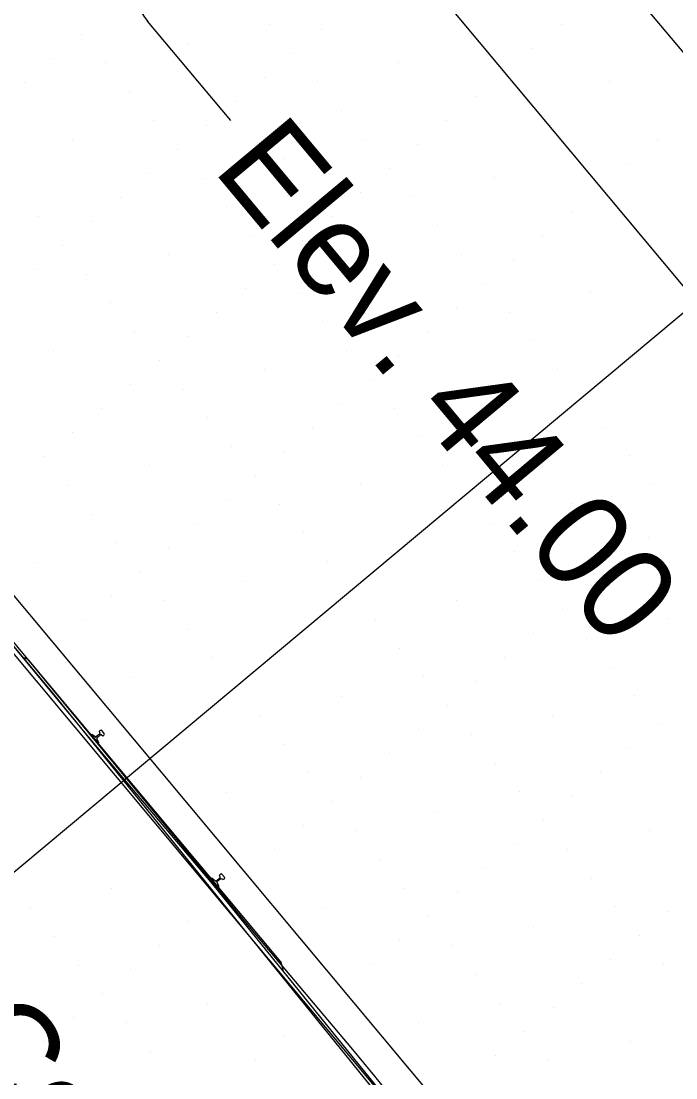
# Model space of a CAD drawing. Extents: x 2042995 to 2043795, y 305365 to 306249.
# Drawn here: x 2043333.05 to 2043350.52, y 305730.9 to 305759.09 of the extents above; entities that cross this region are included whole.
import ezdxf

# ---------------------------------------------------------------- set-up
doc = ezdxf.new("R2010")
doc.units = 0
for name, color, linetype in [('BR_AUTO DIMENSION', 7, 'Continuous'), ('BR_CONCRETE', 7, 'Continuous'), ('BR_EXIST_GROUND_CL', 7, 'Continuous'), ('BR_EXIST_GROUND_LT', 7, 'Continuous'), ('BR_EXIST_GROUND_RT', 7, 'Continuous'), ('BR_GRID DOTS', 7, 'Continuous'), ('BR_GRID LINES', 7, 'Continuous'), ('BR_GROUND LINES', 7, 'Continuous'), ('BR_PRESTRESSED BEAM', 7, 'Continuous'), ('BR_STRUCTURAL STEEL', 7, 'Continuous'), ('BR_TEXT', 7, 'Continuous')]:
    doc.layers.add(name, color=color, linetype=linetype)

msp = doc.modelspace()

# ---------------------------------------------------------------- linework, layer by layer
at = {"layer": 'BR_AUTO DIMENSION'}
for p, q in [((2043320.869, 305793.992), (2043366.621, 305739.212)), ((2043303.216, 305779.248), (2043348.968, 305724.468)), ((2043338.646, 305756.435), (2043336.429, 305759.091))]:
    msp.add_line(p, q, dxfattribs=at)
msp.add_arc((2043337.708, 305760.159), 1.667, 129.8684, 219.8684, dxfattribs=at)
at = {"layer": 'BR_CONCRETE'}
for points in [[(2043139.109, 306017.548), (2043148.199, 306007.16), (2043160.233, 305993.368), (2043172.245, 305979.557), (2043184.234, 305965.727), (2043196.201, 305951.879), (2043208.145, 305938.012), (2043220.067, 305924.126), (2043231.966, 305910.221), (2043243.843, 305896.297), (2043255.698, 305882.355), (2043267.529, 305868.394), (2043279.339, 305854.414), (2043291.126, 305840.415), (2043302.89, 305826.398), (2043314.632, 305812.361), (2043326.352, 305798.306), (2043338.049, 305784.233), (2043349.724, 305770.14), (2043361.376, 305756.029), (2043373.005, 305741.899), (2043384.613, 305727.75), (2043396.197, 305713.582), (2043407.76, 305699.396), (2043419.299, 305685.191), (2043430.817, 305670.967), (2043442.311, 305656.724), (2043453.784, 305642.463), (2043465.234, 305628.182), (2043476.661, 305613.883), (2043488.066, 305599.566), (2043499.448, 305585.229), (2043510.808, 305570.874), (2043522.146, 305556.5), (2043533.461, 305542.107), (2043544.753, 305527.695), (2043547.219, 305524.543)], [(2043273.14, 305860.139), (2043278.86, 305853.362), (2043290.647, 305839.364), (2043302.411, 305825.346), (2043314.153, 305811.31), (2043325.873, 305797.255), (2043337.57, 305783.181), (2043349.245, 305769.089), (2043360.897, 305754.977), (2043372.526, 305740.847), (2043384.134, 305726.698), (2043395.718, 305712.531), (2043407.281, 305698.344), (2043418.82, 305684.139), (2043425.623, 305675.744)]]:
    msp.add_spline(points, degree=3, dxfattribs=at)
at = {"layer": 'BR_EXIST_GROUND_CL'}
msp.add_lwpolyline([(2043308.08, 305802.975), (2043311.357, 305794.254), (2043312.201, 305793.367), (2043312.31, 305791.765), (2043310.711, 305789.675), (2043302.424, 305778.884), (2043307.323, 305773.564), (2043309.247, 305771.475), (2043312.233, 305767.935), (2043312.545, 305767.564), (2043317.632, 305761.139), (2043321.959, 305755.674), (2043324.878, 305751.989), (2043325.714, 305750.99), (2043328.169, 305748.055), (2043331.001, 305744.638), (2043334.846, 305739.998), (2043336.813, 305737.66), (2043338.156, 305736.064), (2043343.356, 305729.655)], dxfattribs=at)
at = {"layer": 'BR_EXIST_GROUND_LT'}
msp.add_lwpolyline([(2043306.871, 305795.372), (2043298.097, 305784.008), (2043302.538, 305779.189), (2043304.941, 305776.583), (2043307.803, 305773.186), (2043308.238, 305772.67), (2043315.324, 305763.737), (2043320.576, 305757.115), (2043320.901, 305756.726), (2043323.864, 305753.181), (2043328.979, 305747.048), (2043330.565, 305745.131), (2043331.485, 305744.037), (2043333.871, 305741.191), (2043345.181, 305727.208)], dxfattribs=at)
at = {"layer": 'BR_EXIST_GROUND_RT'}
msp.add_lwpolyline([(2043311.795, 305797.361), (2043312.912, 305786.83), (2043313.335, 305784.229), (2043315.447, 305785.237), (2043313.716, 305783.437), (2043313.135, 305782.673), (2043309.838, 305778.182), (2043306.75, 305773.76), (2043310.033, 305770.195), (2043313.561, 305766.363), (2043315.546, 305764.008), (2043316.86, 305762.451), (2043321.605, 305756.461), (2043329.201, 305746.882), (2043331.305, 305744.369), (2043332.491, 305742.951), (2043337.468, 305736.946), (2043339.175, 305734.886), (2043341.892, 305731.649), (2043342.483, 305730.946), (2043346.769, 305725.658)], dxfattribs=at)
at = {"layer": 'BR_GRID DOTS'}
for p, q in [((2043339.667, 305759.004), (2043339.667, 305759.004)), ((2043341.075, 305758.878), (2043341.075, 305758.878)), ((2043347.477, 305759.013), (2043347.477, 305759.013)), ((2043334.674, 305758.743), (2043334.674, 305758.743)), ((2043337.491, 305758.49), (2043337.491, 305758.49)), ((2043350.294, 305758.76), (2043350.294, 305758.76)), ((2043340.308, 305758.237), (2043340.308, 305758.237)), ((2043346.709, 305758.372), (2043346.709, 305758.372)), ((2043333.906, 305758.102), (2043333.906, 305758.102)), ((2043335.315, 305757.975), (2043335.315, 305757.975)), ((2043343.125, 305757.984), (2043343.125, 305757.984)), ((2043345.942, 305757.731), (2043345.942, 305757.731)), ((2043333.139, 305757.461), (2043333.139, 305757.461)), ((2043339.54, 305757.596), (2043339.54, 305757.596)), ((2043340.949, 305757.469), (2043340.949, 305757.469)), ((2043348.759, 305757.478), (2043348.759, 305757.478)), ((2043335.956, 305757.208), (2043335.956, 305757.208)), ((2043345.174, 305757.09), (2043345.174, 305757.09)), ((2043338.773, 305756.955), (2043338.773, 305756.955)), ((2043341.59, 305756.702), (2043341.59, 305756.702)), ((2043336.597, 305756.44), (2043336.597, 305756.44)), ((2043338.005, 305756.314), (2043338.005, 305756.314)), ((2043344.407, 305756.449), (2043344.407, 305756.449)), ((2043334.421, 305755.926), (2043334.421, 305755.926)), ((2043337.238, 305755.673), (2043337.238, 305755.673)), ((2043342.231, 305755.934), (2043342.231, 305755.934)), ((2043343.639, 305755.808), (2043343.639, 305755.808)), ((2043350.041, 305755.943), (2043350.041, 305755.943)), ((2043340.055, 305755.42), (2043340.055, 305755.42)), ((2043342.872, 305755.167), (2043342.872, 305755.167)), ((2043349.274, 305755.302), (2043349.274, 305755.302)), ((2043336.47, 305755.032), (2043336.47, 305755.032)), ((2043337.879, 305754.905), (2043337.879, 305754.905)), ((2043345.689, 305754.914), (2043345.689, 305754.914)), ((2043348.506, 305754.661), (2043348.506, 305754.661)), ((2043335.703, 305754.391), (2043335.703, 305754.391)), ((2043342.104, 305754.526), (2043342.104, 305754.526)), ((2043343.513, 305754.399), (2043343.513, 305754.399)), ((2043338.52, 305754.138), (2043338.52, 305754.138)), ((2043347.739, 305754.02), (2043347.739, 305754.02)), ((2043333.527, 305753.876), (2043333.527, 305753.876)), ((2043334.935, 305753.75), (2043334.935, 305753.75)), ((2043341.337, 305753.885), (2043341.337, 305753.885)), ((2043344.154, 305753.632), (2043344.154, 305753.632)), ((2043339.161, 305753.37), (2043339.161, 305753.37)), ((2043340.569, 305753.244), (2043340.569, 305753.244)), ((2043346.971, 305753.379), (2043346.971, 305753.379)), ((2043334.168, 305753.109), (2043334.168, 305753.109)), ((2043336.985, 305752.856), (2043336.985, 305752.856)), ((2043344.795, 305752.864), (2043344.795, 305752.864)), ((2043339.802, 305752.603), (2043339.802, 305752.603)), ((2043346.203, 305752.738), (2043346.203, 305752.738)), ((2043333.4, 305752.468), (2043333.4, 305752.468)), ((2043334.809, 305752.341), (2043334.809, 305752.341)), ((2043342.619, 305752.35), (2043342.619, 305752.35)), ((2043345.436, 305752.097), (2043345.436, 305752.097)), ((2043339.034, 305751.962), (2043339.034, 305751.962)), ((2043340.443, 305751.835), (2043340.443, 305751.835)), ((2043348.253, 305751.844), (2043348.253, 305751.844)), ((2043335.45, 305751.574), (2043335.45, 305751.574)), ((2043344.668, 305751.456), (2043344.668, 305751.456)), ((2043338.267, 305751.321), (2043338.267, 305751.321)), ((2043346.077, 305751.329), (2043346.077, 305751.329)), ((2043341.084, 305751.068), (2043341.084, 305751.068)), ((2043336.091, 305750.806), (2043336.091, 305750.806)), ((2043337.499, 305750.68), (2043337.499, 305750.68)), ((2043343.901, 305750.815), (2043343.901, 305750.815)), ((2043346.718, 305750.562), (2043346.718, 305750.562)), ((2043333.915, 305750.292), (2043333.915, 305750.292)), ((2043336.732, 305750.039), (2043336.732, 305750.039)), ((2043341.725, 305750.3), (2043341.725, 305750.3)), ((2043343.133, 305750.174), (2043343.133, 305750.174)), ((2043339.549, 305749.786), (2043339.549, 305749.786)), ((2043347.359, 305749.794), (2043347.359, 305749.794)), ((2043342.366, 305749.533), (2043342.366, 305749.533)), ((2043335.964, 305749.398), (2043335.964, 305749.398)), ((2043337.373, 305749.271), (2043337.373, 305749.271)), ((2043345.183, 305749.28), (2043345.183, 305749.28)), ((2043335.197, 305748.757), (2043335.197, 305748.757)), ((2043341.598, 305748.892), (2043341.598, 305748.892)), ((2043343.007, 305748.765), (2043343.007, 305748.765)), ((2043338.014, 305748.504), (2043338.014, 305748.504)), ((2043334.429, 305748.116), (2043334.429, 305748.116)), ((2043340.831, 305748.251), (2043340.831, 305748.251)), ((2043348.641, 305748.259), (2043348.641, 305748.259)), ((2043343.648, 305747.998), (2043343.648, 305747.998)), ((2043338.655, 305747.736), (2043338.655, 305747.736)), ((2043340.063, 305747.61), (2043340.063, 305747.61)), ((2043349.282, 305747.492), (2043349.282, 305747.492)), ((2043333.662, 305747.475), (2043333.662, 305747.475)), ((2043336.479, 305747.222), (2043336.479, 305747.222)), ((2043344.289, 305747.23), (2043344.289, 305747.23)), ((2043339.296, 305746.969), (2043339.296, 305746.969)), ((2043334.303, 305746.707), (2043334.303, 305746.707)), ((2043342.113, 305746.716), (2043342.113, 305746.716)), ((2043349.923, 305746.724), (2043349.923, 305746.724)), ((2043338.528, 305746.328), (2043338.528, 305746.328)), ((2043339.937, 305746.201), (2043339.937, 305746.201)), ((2043347.747, 305746.21), (2043347.747, 305746.21)), ((2043334.944, 305745.94), (2043334.944, 305745.94)), ((2043337.761, 305745.687), (2043337.761, 305745.687)), ((2043345.571, 305745.695), (2043345.571, 305745.695)), ((2043340.578, 305745.434), (2043340.578, 305745.434)), ((2043349.797, 305745.316), (2043349.797, 305745.316)), ((2043335.585, 305745.172), (2043335.585, 305745.172)), ((2043336.993, 305745.045), (2043336.993, 305745.045)), ((2043346.212, 305744.928), (2043346.212, 305744.928)), ((2043349.029, 305744.675), (2043349.029, 305744.675)), ((2043333.409, 305744.657), (2043333.409, 305744.657)), ((2043336.226, 305744.404), (2043336.226, 305744.404)), ((2043341.219, 305744.666), (2043341.219, 305744.666)), ((2043339.043, 305744.151), (2043339.043, 305744.151)), ((2043346.853, 305744.16), (2043346.853, 305744.16)), ((2043348.262, 305744.034), (2043348.262, 305744.034)), ((2043335.458, 305743.763), (2043335.458, 305743.763)), ((2043336.867, 305743.637), (2043336.867, 305743.637)), ((2043344.677, 305743.646), (2043344.677, 305743.646)), ((2043347.494, 305743.393), (2043347.494, 305743.393)), ((2043334.691, 305743.122), (2043334.691, 305743.122)), ((2043342.501, 305743.131), (2043342.501, 305743.131)), ((2043350.311, 305743.14), (2043350.311, 305743.14)), ((2043337.508, 305742.869), (2043337.508, 305742.869)), ((2043346.727, 305742.751), (2043346.727, 305742.751)), ((2043333.923, 305742.481), (2043333.923, 305742.481)), ((2043348.135, 305742.625), (2043348.135, 305742.625)), ((2043343.142, 305742.363), (2043343.142, 305742.363)), ((2043338.149, 305742.102), (2043338.149, 305742.102)), ((2043345.959, 305742.11), (2043345.959, 305742.11)), ((2043348.776, 305741.857), (2043348.776, 305741.857)), ((2043333.156, 305741.84), (2043333.156, 305741.84)), ((2043335.973, 305741.587), (2043335.973, 305741.587)), ((2043343.783, 305741.596), (2043343.783, 305741.596)), ((2043345.192, 305741.469), (2043345.192, 305741.469)), ((2043341.607, 305741.081), (2043341.607, 305741.081)), ((2043349.417, 305741.09), (2043349.417, 305741.09)), ((2043344.424, 305740.828), (2043344.424, 305740.828)), ((2043339.431, 305740.567), (2043339.431, 305740.567)), ((2043347.241, 305740.575), (2043347.241, 305740.575)), ((2043343.656, 305740.187), (2043343.656, 305740.187)), ((2043350.058, 305740.322), (2043350.058, 305740.322)), ((2043345.065, 305740.061), (2043345.065, 305740.061)), ((2043340.072, 305739.799), (2043340.072, 305739.799)), ((2043349.291, 305739.681), (2043349.291, 305739.681)), ((2043342.889, 305739.546), (2043342.889, 305739.546)), ((2043345.706, 305739.293), (2043345.706, 305739.293)), ((2043348.523, 305739.04), (2043348.523, 305739.04)), ((2043340.713, 305739.032), (2043340.713, 305739.032)), ((2043342.121, 305738.905), (2043342.121, 305738.905)), ((2043338.537, 305738.517), (2043338.537, 305738.517)), ((2043346.347, 305738.526), (2043346.347, 305738.526)), ((2043341.354, 305738.264), (2043341.354, 305738.264)), ((2043347.756, 305738.399), (2043347.756, 305738.399)), ((2043344.171, 305738.011), (2043344.171, 305738.011)), ((2043340.586, 305737.623), (2043340.586, 305737.623)), ((2043346.988, 305737.758), (2043346.988, 305737.758)), ((2043341.995, 305737.497), (2043341.995, 305737.497)), ((2043349.805, 305737.505), (2043349.805, 305737.505)), ((2043346.221, 305737.117), (2043346.221, 305737.117)), ((2043339.819, 305736.982), (2043339.819, 305736.982)), ((2043347.629, 305736.991), (2043347.629, 305736.991)), ((2043342.636, 305736.729), (2043342.636, 305736.729)), ((2043339.051, 305736.341), (2043339.051, 305736.341)), ((2043345.453, 305736.476), (2043345.453, 305736.476)), ((2043348.27, 305736.223), (2043348.27, 305736.223)), ((2043335.467, 305735.953), (2043335.467, 305735.953)), ((2043343.277, 305735.962), (2043343.277, 305735.962)), ((2043338.284, 305735.7), (2043338.284, 305735.7)), ((2043344.686, 305735.835), (2043344.686, 305735.835)), ((2043333.291, 305735.439), (2043333.291, 305735.439)), ((2043341.101, 305735.447), (2043341.101, 305735.447)), ((2043348.911, 305735.456), (2043348.911, 305735.456)), ((2043343.918, 305735.194), (2043343.918, 305735.194)), ((2043350.32, 305735.329), (2043350.32, 305735.329)), ((2043337.516, 305735.059), (2043337.516, 305735.059)), ((2043346.735, 305734.941), (2043346.735, 305734.941)), ((2043333.932, 305734.671), (2043333.932, 305734.671)), ((2043343.151, 305734.553), (2043343.151, 305734.553)), ((2043349.552, 305734.688), (2043349.552, 305734.688)), ((2043336.749, 305734.418), (2043336.749, 305734.418)), ((2043344.559, 305734.427), (2043344.559, 305734.427)), ((2043348.785, 305734.047), (2043348.785, 305734.047)), ((2043334.573, 305733.904), (2043334.573, 305733.904)), ((2043335.981, 305733.777), (2043335.981, 305733.777)), ((2043342.383, 305733.912), (2043342.383, 305733.912)), ((2043350.193, 305733.921), (2043350.193, 305733.921)), ((2043345.2, 305733.659), (2043345.2, 305733.659)), ((2043348.017, 305733.406), (2043348.017, 305733.406)), ((2043335.214, 305733.136), (2043335.214, 305733.136)), ((2043341.615, 305733.271), (2043341.615, 305733.271)), ((2043338.031, 305732.883), (2043338.031, 305732.883)), ((2043345.841, 305732.892), (2043345.841, 305732.892)), ((2043340.848, 305732.63), (2043340.848, 305732.63)), ((2043347.25, 305732.765), (2043347.25, 305732.765)), ((2043334.446, 305732.495), (2043334.446, 305732.495)), ((2043335.855, 305732.369), (2043335.855, 305732.369)), ((2043343.665, 305732.377), (2043343.665, 305732.377)), ((2043340.08, 305731.989), (2043340.08, 305731.989)), ((2043346.482, 305732.124), (2043346.482, 305732.124)), ((2043333.679, 305731.854), (2043333.679, 305731.854)), ((2043349.299, 305731.871), (2043349.299, 305731.871)), ((2043336.496, 305731.601), (2043336.496, 305731.601)), ((2043345.715, 305731.483), (2043345.715, 305731.483)), ((2043339.313, 305731.348), (2043339.313, 305731.348)), ((2043347.123, 305731.357), (2043347.123, 305731.357))]:
    msp.add_line(p, q, dxfattribs=at)
at = {"layer": 'BR_GRID LINES'}
for p, q in [((2043122.438, 306025.339), (2043554.061, 305508.544)), ((2043194.694, 305907.624), (2043538.711, 305495.723)), ((2043412.472, 305802.873), (2043258.968, 305674.668))]:
    msp.add_line(p, q, dxfattribs=at)
at = {"layer": 'BR_GROUND LINES'}
for p, q in [((2043333.253, 305742.049), (2043333.087, 305742.121)), ((2043339.984, 305733.99), (2043333.253, 305742.049)), ((2043339.984, 305733.99), (2043340.043, 305733.738))]:
    msp.add_line(p, q, dxfattribs=at)
at = {"layer": 'BR_PRESTRESSED BEAM'}
msp.add_spline([(2043269.336, 305856.962), (2043274.734, 305850.568), (2043286.521, 305836.569), (2043298.285, 305822.551), (2043310.027, 305808.515), (2043321.747, 305794.46), (2043333.444, 305780.386), (2043345.119, 305766.294), (2043356.771, 305752.183), (2043368.4, 305738.053), (2043380.007, 305723.904), (2043391.592, 305709.736), (2043403.154, 305695.55), (2043414.694, 305681.345), (2043421.811, 305672.561)], degree=3, dxfattribs=at)
at = {"layer": 'BR_STRUCTURAL STEEL'}
for p, q in [((2043335.17, 305740.168), (2043335.139, 305740.143)), ((2043335.273, 305740.085), (2043335.206, 305740.165)), ((2043334.936, 305740.062), (2043334.926, 305740.053)), ((2043334.926, 305740.046), (2043335.106, 305739.83)), ((2043335.032, 305739.994), (2043334.943, 305740.062)), ((2043335.152, 305740.073), (2043335.058, 305739.995)), ((2043335.124, 305739.844), (2043335.074, 305739.944)), ((2043335.079, 305739.97), (2043335.172, 305740.048)), ((2043335.137, 305740.136), (2043335.157, 305740.098)), ((2043335.198, 305740.048), (2043335.232, 305740.023)), ((2043335.239, 305740.023), (2043335.27, 305740.048)), ((2043335.113, 305739.83), (2043335.123, 305739.838)), ((2043338.131, 305736.216), (2043338.141, 305736.224)), ((2043338.148, 305736.224), (2043338.237, 305736.156)), ((2043338.263, 305736.157), (2043338.357, 305736.235)), ((2043338.362, 305736.261), (2043338.343, 305736.299)), ((2043338.344, 305736.305), (2043338.375, 305736.331)), ((2043338.411, 305736.328), (2043338.478, 305736.248)), ((2043338.311, 305735.993), (2043338.131, 305736.209)), ((2043338.279, 305736.107), (2043338.33, 305736.007)), ((2043338.378, 305736.21), (2043338.284, 305736.132)), ((2043338.328, 305736), (2043338.318, 305735.992)), ((2043338.438, 305736.185), (2043338.403, 305736.211)), ((2043338.475, 305736.211), (2043338.444, 305736.185))]:
    msp.add_line(p, q, dxfattribs=at)
for centre, radius, start, end in [((2043335.186, 305740.148), 0.026, 39.8684, 129.8684), ((2043334.93, 305740.049), 0.00521, 129.8684, 219.8684), ((2043334.939, 305740.058), 0.00521, 52.8684, 129.8684), ((2043335.045, 305740.011), 0.0208, 232.8684, 309.8684), ((2043335.092, 305739.954), 0.0208, 129.8684, 206.8684), ((2043335.142, 305740.139), 0.00521, 129.8684, 206.8684), ((2043335.138, 305740.089), 0.0208, 309.8684, 26.8684), ((2043335.186, 305740.032), 0.0208, 52.8684, 129.8684), ((2043335.236, 305740.027), 0.00521, 232.8684, 309.8684), ((2043335.253, 305740.068), 0.026, 309.8684, 39.8684), ((2043335.11, 305739.834), 0.00521, 219.8684, 309.8684), ((2043335.12, 305739.842), 0.00521, 309.8684, 26.8684), ((2043338.135, 305736.212), 0.00521, 129.8684, 219.8684), ((2043338.145, 305736.22), 0.00521, 52.8684, 129.8684), ((2043338.347, 305736.301), 0.00521, 129.8684, 206.8684), ((2043338.343, 305736.251), 0.0208, 309.8684, 26.8684), ((2043338.391, 305736.311), 0.026, 39.8684, 129.8684), ((2043338.391, 305736.194), 0.0208, 52.8684, 129.8684), ((2043338.458, 305736.231), 0.026, 309.8684, 39.8684), ((2043338.25, 305736.173), 0.0208, 232.8684, 309.8684), ((2043338.297, 305736.116), 0.0208, 129.8684, 206.8684), ((2043338.315, 305735.996), 0.00521, 219.8684, 309.8684), ((2043338.325, 305736.004), 0.00521, 309.8684, 26.8684), ((2043338.441, 305736.189), 0.00521, 232.8684, 309.8684)]:
    msp.add_arc(centre, radius, start, end, dxfattribs=at)

# ---------------------------------------------------------------- texts
at = {"layer": 'BR_TEXT'}
for s, height, p in [('SECTION ALONG L US 17A  US 21', 8.12508, (2043221.449, 305763.122)), ('Elev. 44.00', 2.5, (2043338.141, 305755.131)), ('Concrete Column (Typ.)', 2.5, (2043321.747, 305742.945))]:
    msp.add_text(s, height=height, rotation=309.8684, dxfattribs=at).set_placement(p)

doc.saveas('drawing.dxf')
